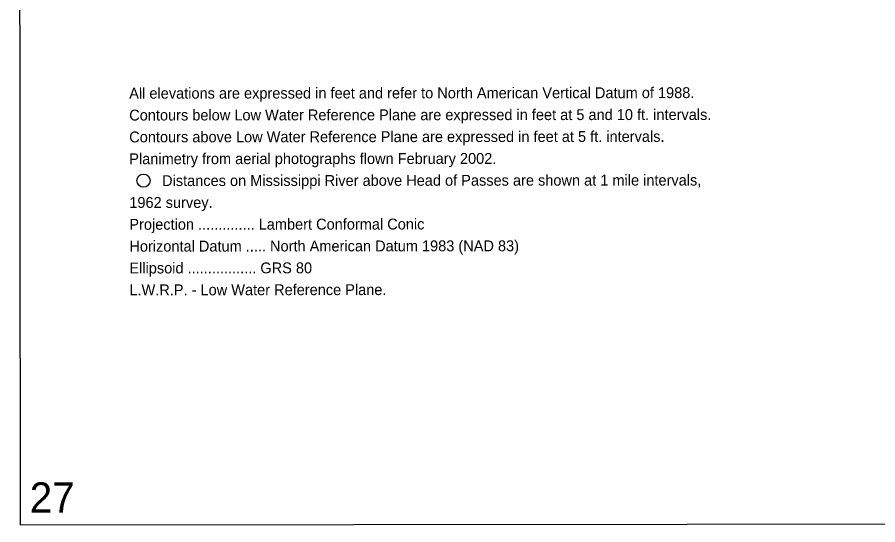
# Model space of a CAD drawing. Extents: x 3297735 to 3335592, y 670436 to 695807.
# Drawn here: x 3301069 to 3307635, y 671647 to 675520 of the extents above; entities that cross this region are included whole.
import ezdxf

# ---------------------------------------------------------------- set-up
doc = ezdxf.new("R2010")
doc.units = 0
for name, color, linetype in [('V-ANNO-NOTE', 7, 'Continuous'), ('V-ANNO-SYMB', 7, 'Continuous'), ('V-ANNO-TEXT', 7, 'Continuous')]:
    doc.layers.add(name, color=color, linetype=linetype)

msp = doc.modelspace()

# ---------------------------------------------------------------- linework, layer by layer
at = {"layer": 'V-ANNO-NOTE'}
msp.add_circle((3302032.1, 674273.2), 50, dxfattribs=at)
at = {"layer": 'V-ANNO-SYMB'}
msp.add_lwpolyline([(3301092, 671647.5), (3334175.2, 671681.1), (3334151.9, 694597.7), (3301068.7, 694564), (3301092, 671647.5)], dxfattribs=at)

# ---------------------------------------------------------------- texts
at = {"layer": 'V-ANNO-NOTE'}
for s, rotation, p in [('All elevations are expressed in feet and refer to North American Vertical Datum of 1988.', 0.05834, (3301923.3, 674898.4)), ('Contours below Low Water Reference Plane are expressed in feet at 5 and 10 ft. intervals.', 0.05834, (3301923.4, 674731.7)), ('Contours above Low Water Reference Plane are expressed in feet at 5 ft. intervals.', 0.05834, (3301923.6, 674565)), ('Planimetry from aerial photographs flown February 2002.', 0.05834, (3301923.8, 674398.3)), ('Distances on Mississippi River above Head of Passes are shown at 1 mile intervals,', 0.05834, (3302174.1, 674231.8)), ('1962 survey.', 0.05834, (3301924.1, 674064.9)), ('Projection .............. Lambert Conformal Conic', 0.05831, (3301924.3, 673898.2)), ('Horizontal Datum ..... North American Datum 1983 (NAD 83)', 0.05831, (3301924.4, 673731.5)), ('Ellipsoid ................. GRS 80', 0.05831, (3301924.6, 673564.8)), ('L.W.R.P. - Low Water Reference Plane.', 0.05831, (3301924.8, 673398.1))]:
    msp.add_text(s, height=83, rotation=rotation, dxfattribs=at).set_placement(p)
at = {"layer": 'V-ANNO-TEXT'}
msp.add_text('27', height=230, rotation=0.0583, dxfattribs=at).set_placement((3301164.6, 671740.9))

doc.saveas('drawing.dxf')
